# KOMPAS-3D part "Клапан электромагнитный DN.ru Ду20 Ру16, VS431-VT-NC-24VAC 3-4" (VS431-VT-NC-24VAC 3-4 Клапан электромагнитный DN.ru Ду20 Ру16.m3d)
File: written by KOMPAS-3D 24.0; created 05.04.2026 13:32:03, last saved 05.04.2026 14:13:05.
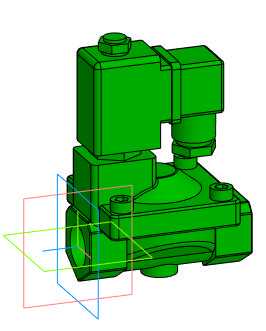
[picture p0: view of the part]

Document properties: Автор: artio; Полное имя файла: C:\Users\artio\OneDrive\Рабочий стол\Клапан электромагнитный DN.ru\VS431\VS431-VT-NC\VS431-VT-NC-24VAC\Ду20\VS431-VT-NC-24VAC 3-4 Клапан электромагнитный DN.ru Ду20 Ру16.m3d

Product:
- Body: Тело 1  | qty 1
    Масса: 1.198355
- Part/product: Клапан электромагнитный DN.ru Ду20 Ру16  | designation VS431-VT-NC-24VAC 3-4
    Масса: 0.907
    Раздел спецификации: Прочие изделия
    Примечание: D130-05513
    additional columns: ef56311e-7521-43dc-8291-0e6108b3d81d; artio; c; Шероховатость не задана; Да

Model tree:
1. Операция без истории:1

Expressions: VS431-VT-NC-24VAC 3-4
